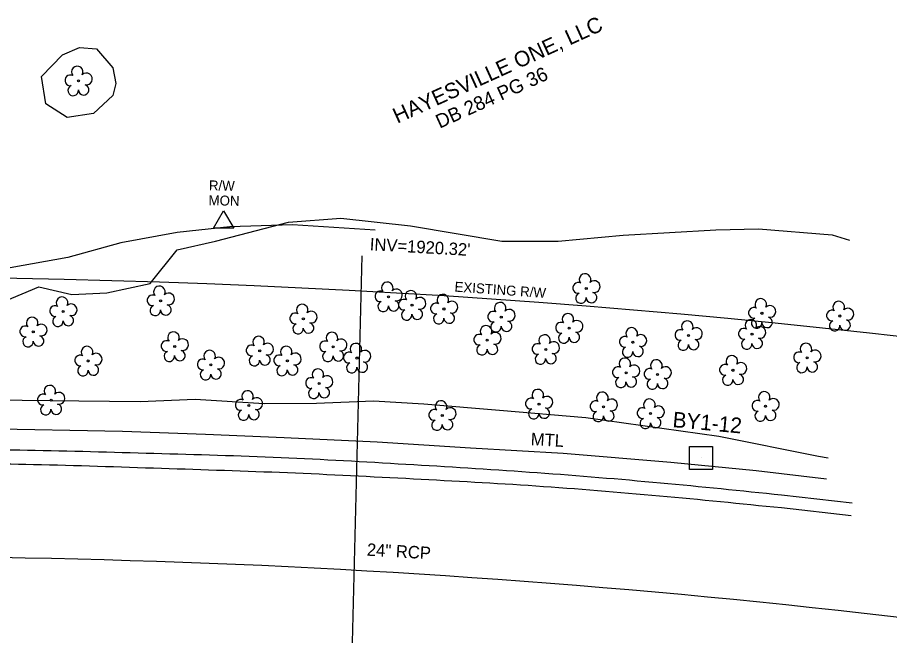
# Model space of a CAD drawing. Extents: x 553786 to 558838, y 502329 to 507342.
# Drawn here: x 554763.6 to 555044.5, y 503062.1 to 503261.4 of the extents above; entities that cross this region are included whole.
import ezdxf

# ---------------------------------------------------------------- set-up
doc = ezdxf.new("R2010")
doc.units = 0
for name, color, linetype in [('CTL Secondary Horizontal and Vertical Text', 7, 'Continuous'), ('Exist Guardrail Text', 7, 'Continuous'), ('Exist Property Deed Book Text', 7, 'Continuous'), ('Exist Property Owner Text', 7, 'Continuous'), ('Exist Right of Way Line Text', 7, 'Continuous'), ('Exist Right of Way Monument Text', 7, 'Continuous'), ('Exist Structure Minor Pipes RCP 24 Inch', 7, 'Continuous'), ('Exist Structure Minor Pipes RCP 24 Inch Invert', 7, 'Continuous'), ('Exist Structure Minor Pipes RCP 24 Inch Text', 7, 'Continuous'), ('Exist Vegetation Hedge Row', 7, 'Continuous'), ('Exist Vegetation Tree CELL', 7, 'Continuous'), ('Prop Drainage Structure Headwall CELL', 7, 'Continuous'), ('Prop Drainage Structure Pipe Alternate 18in', 7, 'Continuous'), ('Prop Drainage Structure Pipe Alternate 24in', 7, 'Continuous'), ('Prop Drainage Structure Pipe Alternate 36in', 7, 'Continuous'), ('Prop Drainage Structure Pipe Elbow Alternate CELL', 7, 'Continuous'), ('Prop Drainage Structure Pipe RCP 15in Class III Label', 7, 'Continuous'), ('Prop Erosion Rip Rap Class B Label', 7, 'Continuous'), ('Sheet Layout Plan Border', 7, 'Continuous')]:
    doc.layers.add(name, color=color, linetype=linetype)

# ---------------------------------------------------------------- blocks, each defined once
blk = doc.blocks.new('CTL SECONDARY HORIZONTAL AND VERTICAL')
at = {"layer": 'Prop Drainage Structure Pipe Alternate 18in'}
blk.add_line((0, 0), (0, 0), dxfattribs=at)
blk.add_lwpolyline([(-0.1043, 0.0004), (0.0005, 0.1052), (0.1055, 0.0002), (0.0007, -0.1047)], close=True, dxfattribs=at)
blk = doc.blocks.new('EXIST RIGHT OF WAY MONUMENT')
at = {"layer": 'Prop Drainage Structure Pipe Elbow Alternate CELL'}
blk.add_line((0, 0), (0, 0), dxfattribs=at)
blk.add_lwpolyline([(-0.065, -0.0378), (0, 0.075), (0.065, -0.0378)], close=True, dxfattribs=at)

msp = doc.modelspace()

# ---------------------------------------------------------------- linework, layer by layer
at = {"layer": 'Exist Structure Minor Pipes RCP 24 Inch'}
msp.add_line((554869.98, 502998.71), (554874.6, 503184.54), dxfattribs=at)
at = {"layer": 'Exist Vegetation Hedge Row'}
for points in [[(554771.4, 503242.29), (554778.15, 503249.29), (554783.64, 503251.67), (554789.12, 503251.21), (554794.32, 503245.13), (554795.26, 503240.03), (554794.35, 503236.19), (554788.07, 503230.41), (554779.65, 503229.14), (554772.81, 503233.53), (554771.4, 503242.29)], [(554759.8, 503170.04), (554770.54, 503174.51), (554781.15, 503172.07), (554792.43, 503172.61), (554806.34, 503175.65), (554815.07, 503186.5), (554827.41, 503189.23), (554850.88, 503195.36), (554867.8, 503196.68), (554890.22, 503194.17), (554919.57, 503189.22), (554937.76, 503189.27), (554958.67, 503191.16), (554988.48, 503192.91), (555002.3, 503193.28), (555025.97, 503191.29), (555031.53, 503189.57)], [(555024.74, 503119.3), (555021.56, 503119.88), (554989.46, 503126.3), (554946.63, 503132.29), (554918.83, 503134.67), (554894.44, 503136.68), (554878.32, 503137.64), (554859.98, 503136.93), (554843.1, 503136.82), (554820.91, 503138.24), (554803.18, 503137.43), (554783.43, 503137.7), (554765.14, 503137.93), (554729.16, 503138.55)]]:
    msp.add_lwpolyline(points, dxfattribs=at)
at = {"layer": 'Exist Vegetation Tree CELL'}
for p, q in [((554783.28, 503240.94), (554783.28, 503240.94)), ((554946.81, 503174.03), (554946.81, 503174.03)), ((554883.12, 503171.34), (554883.12, 503171.34)), ((554809.74, 503170.04), (554809.74, 503170.04)), ((554890.69, 503168.63), (554890.69, 503168.63)), ((554778.37, 503166.57), (554778.37, 503166.57)), ((554900.98, 503167.4), (554900.98, 503167.4)), ((555003.37, 503166.01), (555003.37, 503166.01)), ((555028.48, 503165.14), (555028.48, 503165.14)), ((554855.69, 503164.2), (554855.69, 503164.2)), ((554919.44, 503164.78), (554919.44, 503164.78)), ((554768.74, 503160.02), (554768.74, 503160.02)), ((554941.26, 503161.21), (554941.26, 503161.21)), ((554914.92, 503157.36), (554914.92, 503157.36)), ((554961.81, 503156.66), (554961.81, 503156.66)), ((554979.72, 503158.86), (554979.72, 503158.86)), ((555000.17, 503159.26), (555000.17, 503159.26)), ((554814.26, 503155.3), (554814.26, 503155.3)), ((554841.64, 503153.89), (554841.64, 503153.89)), ((554865.29, 503155.21), (554865.29, 503155.21)), ((554933.74, 503154.36), (554933.74, 503154.36)), ((554872.97, 503151.59), (554872.97, 503151.59)), ((555017.94, 503151.66), (555017.94, 503151.66)), ((554786.42, 503150.65), (554786.42, 503150.65)), ((554825.91, 503149.38), (554825.91, 503149.38)), ((554850.55, 503150.69), (554850.55, 503150.69)), ((554959.61, 503146.85), (554959.61, 503146.85)), ((554969.76, 503146.32), (554969.76, 503146.32)), ((554994.04, 503147.64), (554994.04, 503147.64)), ((554860.75, 503143.38), (554860.75, 503143.38)), ((554774.45, 503138.04), (554774.45, 503138.04)), ((554838.12, 503136.32), (554838.12, 503136.32)), ((554931.58, 503136.76), (554931.58, 503136.76)), ((554952.38, 503135.89), (554952.38, 503135.89)), ((555004.51, 503136.04), (555004.51, 503136.04)), ((554900.44, 503133.09), (554900.44, 503133.09)), ((554967.5, 503133.68), (554967.5, 503133.68))]:
    msp.add_line(p, q, dxfattribs=at)
for centre in [(554783.28, 503240.94), (554946.81, 503174.03), (554883.12, 503171.34), (554809.74, 503170.04), (554890.69, 503168.63), (554778.37, 503166.57), (554900.98, 503167.4), (554919.44, 503164.78), (555003.37, 503166.01), (555028.48, 503165.14), (554855.69, 503164.2), (554768.74, 503160.02), (554941.26, 503161.21), (555000.17, 503159.26), (554914.92, 503157.36), (554961.81, 503156.66), (554979.72, 503158.86), (554814.26, 503155.3), (554841.64, 503153.89), (554865.29, 503155.21), (554933.74, 503154.36), (554786.42, 503150.65), (554850.55, 503150.69), (554872.97, 503151.59), (555017.94, 503151.66), (554825.91, 503149.38), (554959.61, 503146.85), (554969.76, 503146.32), (554994.04, 503147.64), (554860.75, 503143.38), (554774.45, 503138.04), (554931.58, 503136.76), (554838.12, 503136.32), (554952.38, 503135.89), (555004.51, 503136.04), (554900.44, 503133.09), (554967.5, 503133.68)]:
    msp.add_circle(centre, 0.326, dxfattribs=at)
for centre, radius, start, end in [((554782.89, 503243.81), 1.86, 330.1651, 219.7134), ((554780.67, 503241.09), 1.73, 62.6636, 279.3457), ((554785.83, 503241.53), 1.9, 257.1011, 134.1999), ((554781.57, 503237.82), 1.69, 111.5671, 6.231), ((554784.95, 503238.04), 1.7, 181.2822, 74.56), ((554946.42, 503176.9), 1.86, 330.1651, 219.7134), ((554949.36, 503174.62), 1.9, 257.1011, 134.1999), ((554809.35, 503172.92), 1.86, 330.1651, 219.7134), ((554882.73, 503174.21), 1.86, 330.1651, 219.7134), ((554885.67, 503171.93), 1.9, 257.1011, 134.1999), ((554944.2, 503174.18), 1.73, 62.6636, 279.3457), ((554777.98, 503169.44), 1.86, 330.1651, 219.7134), ((554807.13, 503170.2), 1.73, 62.6636, 279.3457), ((554812.28, 503170.63), 1.9, 257.1011, 134.1999), ((554880.51, 503171.49), 1.73, 62.6636, 279.3457), ((554890.31, 503171.5), 1.86, 330.1651, 219.7134), ((554893.24, 503169.22), 1.9, 257.1011, 134.1999), ((554900.6, 503170.27), 1.86, 330.1651, 219.7134), ((554945.1, 503170.91), 1.69, 111.5671, 6.231), ((554948.48, 503171.13), 1.7, 181.2822, 74.56), ((555002.99, 503168.88), 1.86, 330.1651, 219.7134), ((554775.76, 503166.72), 1.73, 62.6636, 279.3457), ((554780.92, 503167.16), 1.9, 257.1011, 134.1999), ((554808.03, 503166.92), 1.69, 111.5671, 6.231), ((554811.41, 503167.14), 1.7, 181.2822, 74.56), ((554855.31, 503167.07), 1.86, 330.1651, 219.7134), ((554881.41, 503168.22), 1.69, 111.5671, 6.231), ((554884.79, 503168.44), 1.7, 181.2822, 74.56), ((554888.08, 503168.79), 1.73, 62.6636, 279.3457), ((554898.38, 503167.55), 1.73, 62.6636, 279.3457), ((554903.53, 503167.99), 1.9, 257.1011, 134.1999), ((554919.06, 503167.65), 1.86, 330.1651, 219.7134), ((555000.77, 503166.16), 1.73, 62.6636, 279.3457), ((555005.92, 503166.6), 1.9, 257.1011, 134.1999), ((555028.1, 503168.02), 1.86, 330.1651, 219.7134), ((554776.66, 503163.45), 1.69, 111.5671, 6.231), ((554780.04, 503163.67), 1.7, 181.2822, 74.56), ((554853.09, 503164.35), 1.73, 62.6636, 279.3457), ((554858.24, 503164.79), 1.9, 257.1011, 134.1999), ((554888.99, 503165.51), 1.69, 111.5671, 6.231), ((554892.36, 503165.73), 1.7, 181.2822, 74.56), ((554899.28, 503164.28), 1.69, 111.5671, 6.231), ((554902.66, 503164.5), 1.7, 181.2822, 74.56), ((554916.84, 503164.93), 1.73, 62.6636, 279.3457), ((554921.99, 503165.37), 1.9, 257.1011, 134.1999), ((554940.88, 503164.09), 1.86, 330.1651, 219.7134), ((555025.88, 503165.3), 1.73, 62.6636, 279.3457), ((555031.03, 503165.73), 1.9, 257.1011, 134.1999), ((554768.36, 503162.89), 1.86, 330.1651, 219.7134), ((554771.29, 503160.61), 1.9, 257.1011, 134.1999), ((554853.99, 503161.08), 1.69, 111.5671, 6.231), ((554857.36, 503161.3), 1.7, 181.2822, 74.56), ((554917.74, 503161.66), 1.69, 111.5671, 6.231), ((554921.12, 503161.88), 1.7, 181.2822, 74.56), ((554938.66, 503161.37), 1.73, 62.6636, 279.3457), ((554943.81, 503161.8), 1.9, 257.1011, 134.1999), ((554979.34, 503161.73), 1.86, 330.1651, 219.7134), ((554999.79, 503162.13), 1.86, 330.1651, 219.7134), ((555001.67, 503162.89), 1.69, 111.5671, 6.231), ((555005.04, 503163.11), 1.7, 181.2822, 74.56), ((555026.78, 503162.02), 1.69, 111.5671, 6.231), ((555030.16, 503162.24), 1.7, 181.2822, 74.56), ((554766.14, 503160.17), 1.73, 62.6636, 279.3457), ((554813.87, 503158.17), 1.86, 330.1651, 219.7134), ((554864.91, 503158.08), 1.86, 330.1651, 219.7134), ((554914.54, 503160.23), 1.86, 330.1651, 219.7134), ((554917.47, 503157.94), 1.9, 257.1011, 134.1999), ((554939.56, 503158.09), 1.69, 111.5671, 6.231), ((554942.94, 503158.32), 1.7, 181.2822, 74.56), ((554961.42, 503159.53), 1.86, 330.1651, 219.7134), ((554977.12, 503159.01), 1.73, 62.6636, 279.3457), ((554982.27, 503159.45), 1.9, 257.1011, 134.1999), ((554997.57, 503159.41), 1.73, 62.6636, 279.3457), ((555002.72, 503159.85), 1.9, 257.1011, 134.1999), ((554767.04, 503156.9), 1.69, 111.5671, 6.231), ((554770.41, 503157.12), 1.7, 181.2822, 74.56), ((554811.65, 503155.45), 1.73, 62.6636, 279.3457), ((554816.81, 503155.89), 1.9, 257.1011, 134.1999), ((554841.26, 503156.76), 1.86, 330.1651, 219.7134), ((554862.69, 503155.36), 1.73, 62.6636, 279.3457), ((554867.84, 503155.8), 1.9, 257.1011, 134.1999), ((554912.32, 503157.51), 1.73, 62.6636, 279.3457), ((554933.35, 503157.23), 1.86, 330.1651, 219.7134), ((554936.29, 503154.95), 1.9, 257.1011, 134.1999), ((554959.2, 503156.81), 1.73, 62.6636, 279.3457), ((554964.36, 503157.25), 1.9, 257.1011, 134.1999), ((554978.02, 503155.74), 1.69, 111.5671, 6.231), ((554981.4, 503155.96), 1.7, 181.2822, 74.56), ((554998.47, 503156.14), 1.69, 111.5671, 6.231), ((555001.84, 503156.36), 1.7, 181.2822, 74.56), ((554786.03, 503153.52), 1.86, 330.1651, 219.7134), ((554815.93, 503152.4), 1.7, 181.2822, 74.56), ((554825.52, 503152.25), 1.86, 330.1651, 219.7134), ((554839.04, 503154.04), 1.73, 62.6636, 279.3457), ((554844.19, 503154.48), 1.9, 257.1011, 134.1999), ((554850.17, 503153.56), 1.86, 330.1651, 219.7134), ((554866.97, 503152.31), 1.7, 181.2822, 74.56), ((554872.59, 503154.46), 1.86, 330.1651, 219.7134), ((554875.52, 503152.18), 1.9, 257.1011, 134.1999), ((554913.22, 503154.24), 1.69, 111.5671, 6.231), ((554916.6, 503154.46), 1.7, 181.2822, 74.56), ((554931.13, 503154.51), 1.73, 62.6636, 279.3457), ((554960.1, 503153.54), 1.69, 111.5671, 6.231), ((554963.48, 503153.76), 1.7, 181.2822, 74.56), ((555017.55, 503154.53), 1.86, 330.1651, 219.7134), ((555020.49, 503152.25), 1.9, 257.1011, 134.1999), ((554783.81, 503150.8), 1.73, 62.6636, 279.3457), ((554788.97, 503151.24), 1.9, 257.1011, 134.1999), ((554812.55, 503152.18), 1.69, 111.5671, 6.231), ((554823.3, 503149.53), 1.73, 62.6636, 279.3457), ((554828.45, 503149.96), 1.9, 257.1011, 134.1999), ((554839.94, 503150.77), 1.69, 111.5671, 6.231), ((554843.32, 503150.99), 1.7, 181.2822, 74.56), ((554847.95, 503150.84), 1.73, 62.6636, 279.3457), ((554853.1, 503151.28), 1.9, 257.1011, 134.1999), ((554863.59, 503152.09), 1.69, 111.5671, 6.231), ((554870.37, 503151.74), 1.73, 62.6636, 279.3457), ((554932.03, 503151.24), 1.69, 111.5671, 6.231), ((554935.41, 503151.46), 1.7, 181.2822, 74.56), ((554959.22, 503149.72), 1.86, 330.1651, 219.7134), ((554969.38, 503149.2), 1.86, 330.1651, 219.7134), ((554993.66, 503150.52), 1.86, 330.1651, 219.7134), ((555015.33, 503151.81), 1.73, 62.6636, 279.3457), ((554784.71, 503147.53), 1.69, 111.5671, 6.231), ((554788.09, 503147.75), 1.7, 181.2822, 74.56), ((554848.85, 503147.57), 1.69, 111.5671, 6.231), ((554852.22, 503147.79), 1.7, 181.2822, 74.56), ((554871.27, 503148.47), 1.69, 111.5671, 6.231), ((554874.65, 503148.69), 1.7, 181.2822, 74.56), ((554957, 503147), 1.73, 62.6636, 279.3457), ((554962.16, 503147.44), 1.9, 257.1011, 134.1999), ((554967.16, 503146.48), 1.73, 62.6636, 279.3457), ((554972.31, 503146.91), 1.9, 257.1011, 134.1999), ((554991.44, 503147.8), 1.73, 62.6636, 279.3457), ((554996.59, 503148.23), 1.9, 257.1011, 134.1999), ((555016.24, 503148.54), 1.69, 111.5671, 6.231), ((555019.61, 503148.76), 1.7, 181.2822, 74.56), ((554824.2, 503146.25), 1.69, 111.5671, 6.231), ((554827.58, 503146.48), 1.7, 181.2822, 74.56), ((554860.37, 503146.25), 1.86, 330.1651, 219.7134), ((554863.3, 503143.97), 1.9, 257.1011, 134.1999), ((554961.28, 503143.95), 1.7, 181.2822, 74.56), ((554992.34, 503144.52), 1.69, 111.5671, 6.231), ((554995.71, 503144.75), 1.7, 181.2822, 74.56), ((554774.06, 503140.91), 1.86, 330.1651, 219.7134), ((554858.15, 503143.53), 1.73, 62.6636, 279.3457), ((554957.91, 503143.73), 1.69, 111.5671, 6.231), ((554968.06, 503143.2), 1.69, 111.5671, 6.231), ((554971.43, 503143.42), 1.7, 181.2822, 74.56), ((554771.84, 503138.19), 1.73, 62.6636, 279.3457), ((554776.99, 503138.63), 1.9, 257.1011, 134.1999), ((554837.74, 503139.19), 1.86, 330.1651, 219.7134), ((554859.05, 503140.26), 1.69, 111.5671, 6.231), ((554862.43, 503140.48), 1.7, 181.2822, 74.56), ((554931.19, 503139.64), 1.86, 330.1651, 219.7134), ((554952, 503138.77), 1.86, 330.1651, 219.7134), ((555004.12, 503138.91), 1.86, 330.1651, 219.7134), ((554835.52, 503136.47), 1.73, 62.6636, 279.3457), ((554840.67, 503136.9), 1.9, 257.1011, 134.1999), ((554900.05, 503135.97), 1.86, 330.1651, 219.7134), ((554928.97, 503136.92), 1.73, 62.6636, 279.3457), ((554934.13, 503137.35), 1.9, 257.1011, 134.1999), ((554949.78, 503136.05), 1.73, 62.6636, 279.3457), ((554954.93, 503136.48), 1.9, 257.1011, 134.1999), ((554967.12, 503136.56), 1.86, 330.1651, 219.7134), ((555001.9, 503136.19), 1.73, 62.6636, 279.3457), ((555007.06, 503136.63), 1.9, 257.1011, 134.1999), ((554772.74, 503134.92), 1.69, 111.5671, 6.231), ((554776.12, 503135.14), 1.7, 181.2822, 74.56), ((554836.42, 503133.19), 1.69, 111.5671, 6.231), ((554839.79, 503133.42), 1.7, 181.2822, 74.56), ((554897.83, 503133.25), 1.73, 62.6636, 279.3457), ((554902.99, 503133.68), 1.9, 257.1011, 134.1999), ((554929.87, 503133.64), 1.69, 111.5671, 6.231), ((554933.25, 503133.86), 1.7, 181.2822, 74.56), ((554950.68, 503132.77), 1.69, 111.5671, 6.231), ((554954.06, 503132.99), 1.7, 181.2822, 74.56), ((554964.9, 503133.84), 1.73, 62.6636, 279.3457), ((554970.05, 503134.27), 1.9, 257.1011, 134.1999), ((555002.81, 503132.92), 1.69, 111.5671, 6.231), ((555006.18, 503133.14), 1.7, 181.2822, 74.56), ((554898.73, 503129.97), 1.69, 111.5671, 6.231), ((554902.11, 503130.19), 1.7, 181.2822, 74.56), ((554965.8, 503130.56), 1.69, 111.5671, 6.231), ((554969.17, 503130.78), 1.7, 181.2822, 74.56)]:
    msp.add_arc(centre, radius, start, end, dxfattribs=at)
at = {"layer": 'Prop Drainage Structure Headwall CELL'}
msp.add_line((555032.11, 503100.73), (555009.62, 503103.27), dxfattribs=at)
msp.add_spline([(555009.62, 503103.27), (554970.38, 503107.1), (554930.52, 503110.3), (554891.2, 503112.58), (554850.59, 503114.56), (554809.97, 503115.97), (554768.8, 503117.22), (554729.86, 503117.84), (554688.09, 503118.07), (554646.73, 503117.18), (554606.63, 503115.85)], degree=3, dxfattribs=at)
at = {"layer": 'Prop Drainage Structure Pipe Alternate 24in'}
msp.add_lwpolyline([(554878.82, 503192.82), (554852.16, 503194.58), (554832.02, 503193.92), (554815.06, 503192.05), (554796.89, 503188.68), (554779.82, 503183.95), (554754, 503179.33), (554725.99, 503176.11)], dxfattribs=at)
msp.add_lwpolyline([(554878.82, 503192.82), (554852.16, 503194.58), (554832.02, 503193.92), (554815.06, 503192.05), (554796.89, 503188.68), (554779.82, 503183.95), (554754, 503179.33), (554725.99, 503176.11)], dxfattribs=at)
at = {"layer": 'Prop Drainage Structure Pipe Alternate 36in'}
msp.add_line((555032.38, 503104.77), (555009.7, 503107.41), dxfattribs=at)
msp.add_spline([(555009.7, 503107.41), (554970.66, 503111.28), (554931.02, 503114.57), (554891.25, 503117.14), (554851.06, 503119.32), (554810.15, 503120.73), (554769.34, 503121.76), (554729.7, 503122.25), (554688.38, 503122.14), (554646.33, 503121.68), (554606.76, 503120.5)], degree=3, dxfattribs=at)
at = {"layer": 'Prop Drainage Structure Pipe RCP 15in Class III Label'}
msp.add_arc((554712.36, 500222.83), 2954.79, 70.63346, 89.60428, dxfattribs=at)
at = {"layer": 'Prop Erosion Rip Rap Class B Label'}
msp.add_lwpolyline([(554631.65, 503127.87), (554688.62, 503128.39), (554752.15, 503128.9), (554797.48, 503128), (554824.16, 503127.08), (554849.5, 503126.01), (554879.46, 503124.63), (554909.48, 503122.66), (554939.34, 503120.93), (554973.98, 503118.02), (555001.52, 503115.37), (555024.11, 503112.71)], dxfattribs=at)
at = {"layer": 'Sheet Layout Plan Border'}
msp.add_arc((554712.36, 500222.83), 2864.79, 70.63346, 92.31986, dxfattribs=at)

# ---------------------------------------------------------------- block references
at = {"layer": 'Prop Drainage Structure Pipe Alternate 18in', "xscale": 50, "yscale": 49.99999999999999, "rotation": 44.99999999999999}
msp.add_blockref('CTL SECONDARY HORIZONTAL AND VERTICAL', (554983.76, 503119.39), dxfattribs=at)
at = {"layer": 'Prop Drainage Structure Pipe Elbow Alternate CELL', "xscale": 50, "yscale": 50}
msp.add_blockref('EXIST RIGHT OF WAY MONUMENT', (554830.02, 503195.29), dxfattribs=at)

# ---------------------------------------------------------------- texts
at = {"layer": 'CTL Secondary Horizontal and Vertical Text'}
msp.add_text('BY1-12', height=5, rotation=354.6356, dxfattribs=at).set_placement((554974.44, 503129.35))
at = {"layer": 'Exist Guardrail Text'}
msp.add_text('MTL', height=4, rotation=356.6841, dxfattribs=at).set_placement((554928.83, 503123.54))
at = {"layer": 'Exist Property Deed Book Text'}
msp.add_text('DB 284 PG 36', height=4.5, rotation=24.4435, dxfattribs=at).set_placement((554899.59, 503225.49))
at = {"layer": 'Exist Property Owner Text'}
msp.add_text('HAYESVILLE ONE, LLC', height=5, rotation=24.4435, dxfattribs=at).set_placement((554885.94, 503227.09))
at = {"layer": 'Exist Right of Way Line Text'}
msp.add_text('EXISTING R/W', height=3.2, rotation=355.9696, dxfattribs=at).set_placement((554904.29, 503173.02))
at = {"layer": 'Exist Right of Way Monument Text'}
for s, p in [('R/W', (554825.25, 503205.66)), ('MON', (554825.14, 503200.87))]:
    msp.add_text(s, height=3.2, rotation=358.6473, dxfattribs=at).set_placement(p)
at = {"layer": 'Exist Structure Minor Pipes RCP 24 Inch Invert'}
msp.add_text("INV=1920.32'", height=4, rotation=356.7194, dxfattribs=at).set_placement((554877, 503186.35))
at = {"layer": 'Exist Structure Minor Pipes RCP 24 Inch Text'}
msp.add_text('24" RCP', height=4, rotation=356.7194, dxfattribs=at).set_placement((554876.06, 503087.9))

doc.saveas('drawing.dxf')
